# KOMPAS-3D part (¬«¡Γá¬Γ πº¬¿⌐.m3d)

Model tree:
1. Эскиз:1
2. Операция выдавливания:1
     Расстояние 1 = 4; Расстояние 2 = 4
3. Эскиз:2
4. Операция выдавливания:2
     Расстояние 1 = 0.5; Расстояние 2 = 8
5. Скругление:1
     Радиус = 0.3
6. Скругление:8
     Радиус = 0.2

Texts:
  stalker61
  Сплав АЛ8  ГОСТ 1583-93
